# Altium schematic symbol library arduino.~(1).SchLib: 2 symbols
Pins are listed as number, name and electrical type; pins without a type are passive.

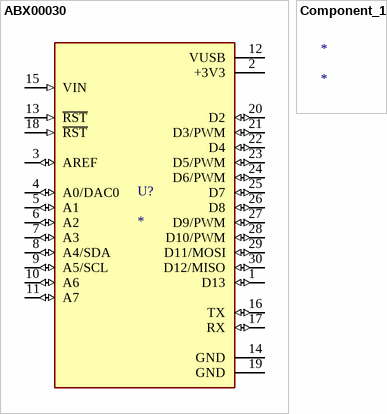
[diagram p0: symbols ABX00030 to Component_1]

## ABX00030
designator U?
NINA-B306, nRF52840 Arduino Nano 33 BLE series ARMÂ® CortexÂ®-M4F MCU 32-Bit Embedded Evaluation Board; MP: ABX00030
footprint MODULE_ABX00030
pins: 1 D13 (io), 2 +3V3 (power), 3 AREF (io), 4 A0/DAC0 (io), 5 A1 (io), 6 A2 (io), 7 A3 (io), 8 A4/SDA (io), 9 A5/SCL (io), 10 A6 (io), 11 A7 (io), 12 VUSB (power), 13 ~{RST} (in), 14 GND (power), 15 VIN (in), 16 TX (io), 17 RX (io), 18 ~{RST} (in), 19 GND (power), 20 D2 (io), 21 D3/PWM (io), 22 D4 (io), 23 D5/PWM (io), 24 D6/PWM (io), 25 D7 (io), 26 D8 (io), 27 D9/PWM (io), 28 D10/PWM (io), 29 D11/MOSI (io), 30 D12/MISO (io)

## Component_1
designator *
